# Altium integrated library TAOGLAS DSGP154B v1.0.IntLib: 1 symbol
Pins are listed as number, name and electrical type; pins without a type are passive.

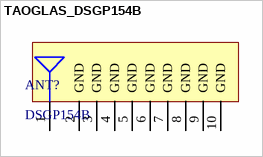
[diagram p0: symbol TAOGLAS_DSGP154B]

## TAOGLAS_DSGP154B
designator ANT?, comment DSGP154B
GPS L1 / GALILEO E1 1575.42MHz 15*15*4mm Ceramic Patch SMD Antenna; ComponentLibStatus: Created; MFG: Taoglas; Temp_High: +85C; Temp_Low: -40C
footprint TAOGLAS_DSGP154B (GPS L1 / GALILEO E1 1575.42MHz 15*15*4mm Ceramic Patch SMD Antenna)
pins: 1 RF FEED, 2 GND, 3 GND, 4 GND, 5 GND, 6 GND, 7 GND, 8 GND, 9 GND, 10 GND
